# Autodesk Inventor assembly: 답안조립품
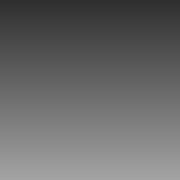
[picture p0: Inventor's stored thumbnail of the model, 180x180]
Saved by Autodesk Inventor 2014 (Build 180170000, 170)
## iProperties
Created: 2015-09
Part Number: 답안조립품
Document SubType Name: Assembly
Designer: Administrator
Author: Administrator
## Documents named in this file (1)
- C:\Users\Administrator\Desktop\450907V1046\답안조립품.iam
